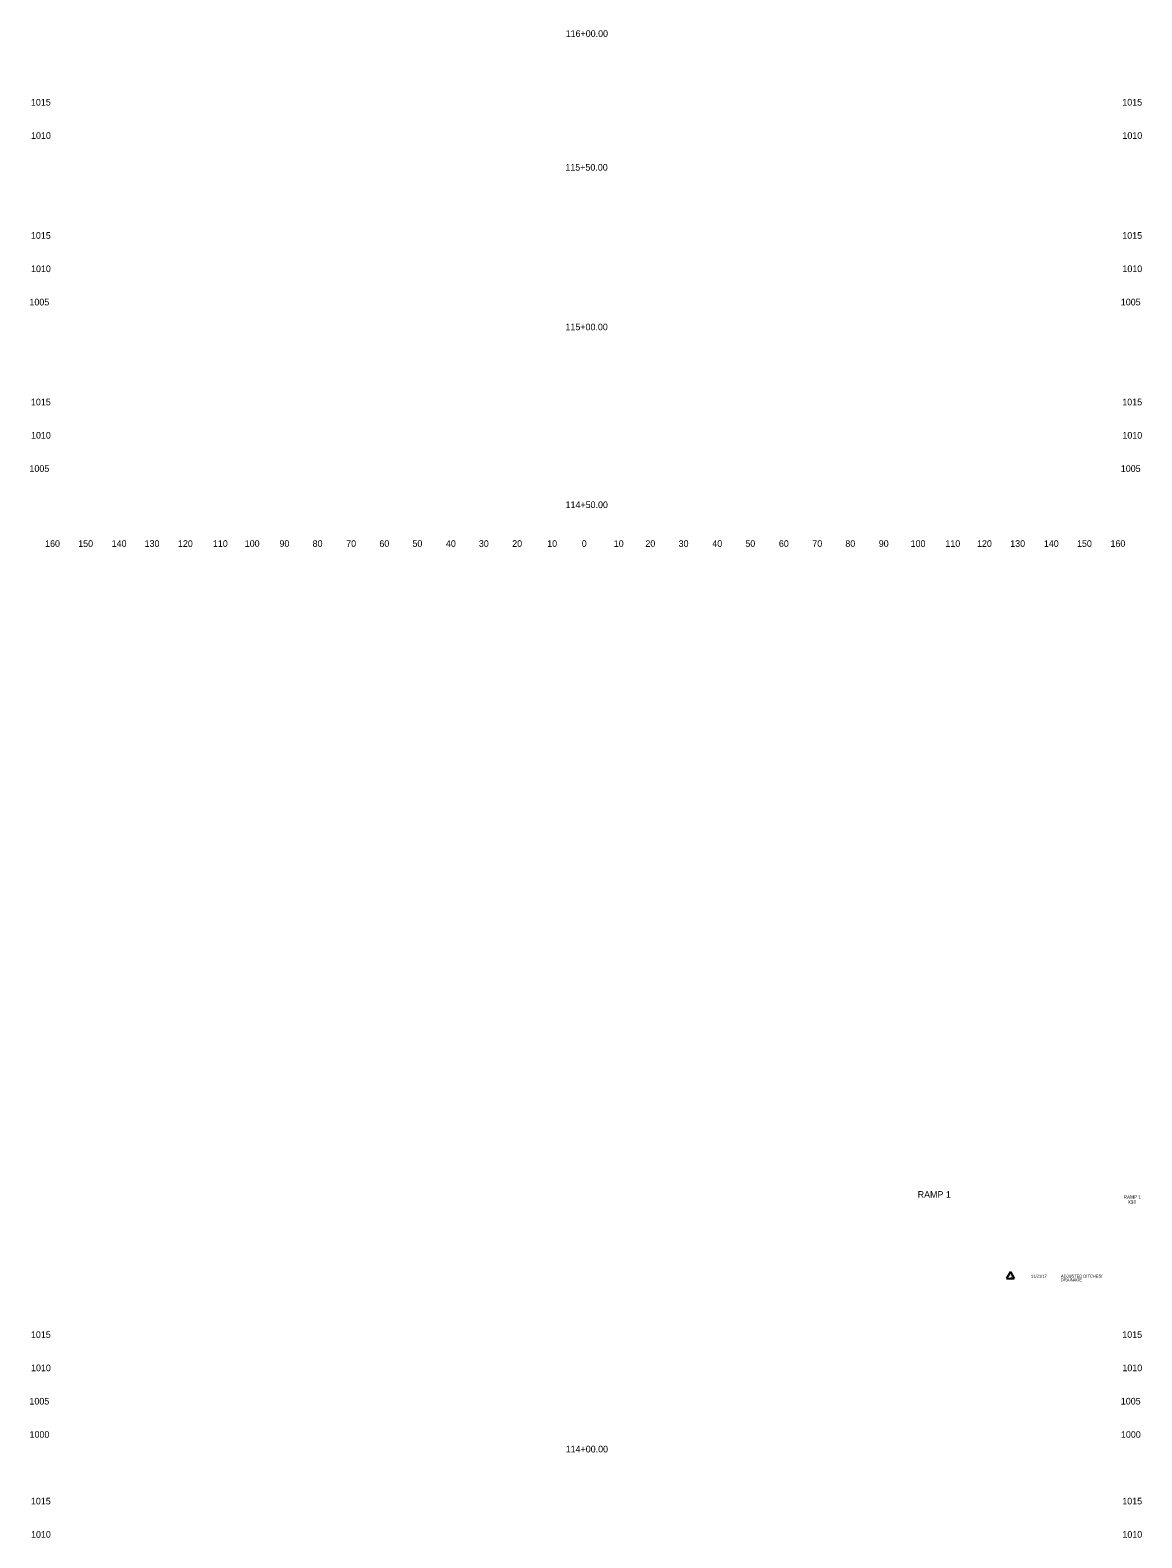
# Model space of a CAD drawing. Extents: x 4994 to 7869, y 4997 to 8804.
# Drawn here: x 6538.6 to 6872.5, y 5900 to 6352.6 of the extents above; entities that cross this region are included whole.
import ezdxf

# ---------------------------------------------------------------- set-up
doc = ezdxf.new("R2010")
doc.units = 0
for name, color, linetype in [('RD_SHT_ID', 7, 'Continuous'), ('RD_SHT_TX', 7, 'Continuous'), ('RD_XS_TX_Offset', 7, 'Continuous'), ('RD_XS_TX_Station', 7, 'Continuous')]:
    doc.layers.add(name, color=color, linetype=linetype)

msp = doc.modelspace()

# ---------------------------------------------------------------- linework, layer by layer
at = {"layer": 'RD_SHT_TX'}
for p, q in [((6833.05, 5979.83), (6831.91, 5977.8)), ((6833.05, 5979.83), (6834.19, 5977.8)), ((6831.91, 5977.8), (6834.19, 5977.8))]:
    msp.add_line(p, q, dxfattribs=at)

# ---------------------------------------------------------------- texts
at = {"layer": 'RD_SHT_ID'}
for s, height, p in [('RAMP 1', 2, (6805.19, 6002.06)), ('RAMP 1', 1, (6867.06, 6001.8)), ('X33', 1, (6868.29, 6000.3))]:
    msp.add_text(s, height=height, dxfattribs=at).set_placement(p)
at = {"layer": 'RD_SHT_TX'}
for s, p in [('1', (6833.05, 5978.13)), ('11/21/17', (6839.24, 5978.09)), ('ADJUSTED DITCHES/', (6848.22, 5978.12)), ('DRAINAGE', (6848.22, 5977.02))]:
    msp.add_text(s, height=0.88, dxfattribs=at).set_placement(p)
at = {"layer": 'RD_XS_TX_Offset'}
for s, p in [('1015', (6538.85, 6330)), ('1015', (6866.65, 6330)), ('1010', (6538.88, 6320)), ('1010', (6866.68, 6320)), ('1015', (6538.85, 6290)), ('1015', (6866.65, 6290)), ('1010', (6538.88, 6280)), ('1010', (6866.68, 6280)), ('1005', (6538.4, 6270)), ('1005', (6866.2, 6270)), ('1015', (6538.85, 6240)), ('1015', (6866.65, 6240)), ('1010', (6538.88, 6230)), ('1010', (6866.68, 6230)), ('1005', (6538.4, 6220)), ('1005', (6866.2, 6220)), ('160', (6543.1, 6197.5)), ('150', (6553.04, 6197.5)), ('140', (6563.1, 6197.5)), ('130', (6572.99, 6197.5)), ('120', (6583.01, 6197.5)), ('110', (6593.51, 6197.5)), ('100', (6603.07, 6197.5)), ('90', (6613.5, 6197.5)), ('80', (6623.46, 6197.5)), ('70', (6633.54, 6197.5)), ('60', (6643.5, 6197.5)), ('50', (6653.43, 6197.5)), ('40', (6663.5, 6197.5)), ('30', (6673.39, 6197.5)), ('20', (6683.4, 6197.5)), ('10', (6693.91, 6197.5)), ('0', (6704.3, 6197.5)), ('0', (6704.3, 6197.5)), ('10', (6713.91, 6197.5)), ('20', (6723.4, 6197.5)), ('30', (6733.39, 6197.5)), ('40', (6743.5, 6197.5)), ('50', (6753.43, 6197.5)), ('60', (6763.5, 6197.5)), ('70', (6773.54, 6197.5)), ('80', (6783.46, 6197.5)), ('90', (6793.5, 6197.5)), ('100', (6803.07, 6197.5)), ('110', (6813.51, 6197.5)), ('120', (6823.01, 6197.5)), ('130', (6832.99, 6197.5)), ('140', (6843.1, 6197.5)), ('150', (6853.04, 6197.5)), ('160', (6863.1, 6197.5)), ('1015', (6538.85, 5960)), ('1015', (6866.65, 5960)), ('1010', (6538.88, 5950)), ('1010', (6866.68, 5950)), ('1005', (6538.4, 5940)), ('1005', (6866.2, 5940)), ('1000', (6538.44, 5930)), ('1000', (6866.24, 5930)), ('1015', (6538.85, 5910)), ('1015', (6866.65, 5910)), ('1010', (6538.88, 5900)), ('1010', (6866.68, 5900))]:
    msp.add_text(s, height=2, dxfattribs=at).set_placement(p)
at = {"layer": 'RD_XS_TX_Station'}
for s, p in [('116+00.00', (6699.46, 6350.61)), ('115+50.00', (6699.37, 6310.46)), ('115+00.00', (6699.4, 6262.54)), ('114+50.00', (6699.43, 6209.15)), ('114+00.00', (6699.46, 5925.62))]:
    msp.add_text(s, height=2, dxfattribs=at).set_placement(p)

doc.saveas('drawing.dxf')
